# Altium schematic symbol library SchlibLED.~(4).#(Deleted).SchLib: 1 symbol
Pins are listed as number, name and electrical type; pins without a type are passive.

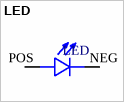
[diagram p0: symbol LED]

## LED
designator LED, comment LHN974_RED_LED_1206  (value not drawn)
2.6 V Red LED SMD; MP: LHN974 RED LED 1206; MF: Osram
footprint LED
pins: NEG, POS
